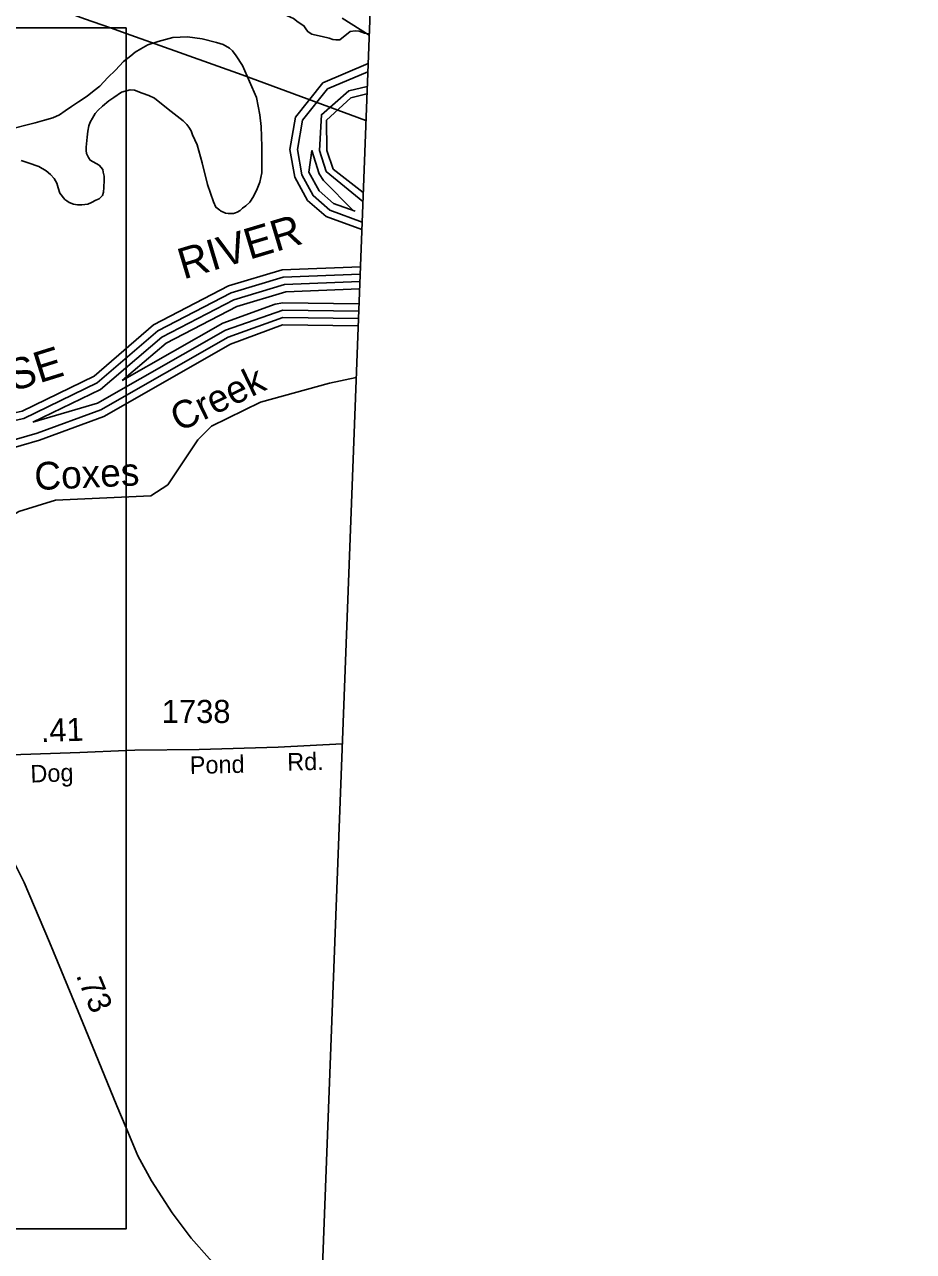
# Model space of a CAD drawing. Extents: x 2206922 to 2357709, y 510027 to 673830.
# Drawn here: x 2347243 to 2352056, y 535608 to 542251 of the extents above; entities that cross this region are included whole.
import ezdxf

# ---------------------------------------------------------------- set-up
doc = ezdxf.new("R2010")
doc.units = 0
for name, color, linetype in [('Exist Boundary Political CountyLine', 7, 'Continuous'), ('Exist Hydrographic Buffer Line', 7, 'Continuous'), ('Exist Hydrographic Creek Single Shore', 7, 'Continuous'), ('Exist Hydrographic Creek Single Shore Label', 7, 'Continuous'), ('Exist Hydrographic Misc Water Feature', 7, 'Continuous'), ('Exist Hydrographic River Shore', 7, 'Continuous'), ('Exist Hydrographic River Shore Label', 7, 'Continuous'), ('Exist Road Primary NC Attributed', 7, 'Continuous'), ('Exist Road Primary NC Service Mileage Hundredths English Label', 7, 'Continuous'), ('Exist Road Secondary Mileage Hundredths English Label', 7, 'Continuous'), ('Exist Road Secondary Type 51 Attributed', 7, 'Continuous'), ('Exist Road Secondary Type 51 Label', 7, 'Continuous'), ('Exist Road Secondary Type 51 Number Label', 7, 'Continuous'), ('Exist Utilities Electrical Transmission Line', 7, 'Continuous'), ('Map Preparation Inset Cut Line', 7, 'Continuous')]:
    doc.layers.add(name, color=color, linetype=linetype)

msp = doc.modelspace()

# ---------------------------------------------------------------- linework, layer by layer
at = {"layer": 'Exist Boundary Political CountyLine'}
msp.add_lwpolyline([(2352055.7, 585131.1), (2350627.1, 582133.9), (2348329.9, 521702.6)], dxfattribs=at)
at = {"layer": 'Exist Hydrographic Buffer Line'}
for points in [[(2349070.3, 541181.2), (2348895.6, 541246.6), (2348805.8, 541324.7), (2348744.3, 541438), (2348719.9, 541574.5), (2348747.6, 541732.6), (2348883.1, 541903.1), (2349101.3, 541995.5)], [(2349098.2, 541915.1), (2348999.4, 541892.4), (2348850.1, 541762.9), (2348839, 541568.9), (2348875.1, 541456.2), (2349074.5, 541292.4)], [(2349032.1, 541240.2), (2348916.3, 541281.7), (2348837.6, 541350.2), (2348782.6, 541451.4), (2348799, 541568.3), (2348837.4, 541443.3), (2348861.6, 541407.6), (2349022.1, 541243.8)], [(2346788.3, 540020.9), (2347238.6, 540118.3), (2347636.6, 540311), (2347963.6, 540592.4), (2348361, 540798.5), (2348643.8, 540883.2), (2349059.6, 540899.9)], [(2347287.4, 540098.5), (2347654, 540275), (2347986.4, 540559.1), (2348376.4, 540761.2), (2348650.4, 540843.4), (2349058.1, 540859.8)], [(2347770.9, 540323.4), (2348008.8, 540525.8), (2348391.4, 540723.9), (2348657.1, 540803.6), (2349056.6, 540819.7)], [(2349053.5, 540739.4), (2348641.3, 540744.4), (2348599.1, 540737.2), (2348316.9, 540633.8), (2347770.9, 540323.4)], [(2349052, 540699.7), (2348640.9, 540704.4), (2348330.7, 540596.2), (2347638, 540201.9), (2347287.4, 540098.5)], [(2349050.5, 540660), (2348640.5, 540664.4), (2348344.4, 540558.7)], [(2348344.4, 540558.7), (2347655, 540165.6), (2347310.6, 540038.4), (2346918.3, 539925.4), (2346462, 539897.4), (2345988.4, 539997.1), (2345590, 540198.4), (2345409.1, 540256.1), (2344967, 540302.7), (2343412.7, 540217.4), (2342470.3, 540107.1), (2341432.7, 539878.5)]]:
    msp.add_lwpolyline(points, dxfattribs=at)
at = {"layer": 'Exist Hydrographic Creek Single Shore'}
msp.add_lwpolyline([(2346448.6, 538412.7), (2346547.1, 538767.8), (2346619.1, 539026.7), (2346692.1, 539183.9), (2346939, 539446.6), (2347212.1, 539615.1), (2347411, 539675.6), (2347927.1, 539699.7), (2348018.2, 539759.2), (2348181.2, 540002), (2348255, 540077.2), (2348520.2, 540206.1), (2348894.2, 540309.7), (2349038.3, 540339.7)], dxfattribs=at)
at = {"layer": 'Exist Hydrographic Misc Water Feature'}
for points in [[(2349109.1, 542200.2), (2349083.6, 542204.7), (2349053.7, 542214.5), (2349033.6, 542216.3), (2349005.5, 542214), (2348950.1, 542169.2), (2348928.4, 542168.8), (2348912.2, 542170.9), (2348892.3, 542176.7), (2348854, 542186.1), (2348812.1, 542195.6), (2348797.8, 542199.4), (2348783.4, 542207.2), (2348775.7, 542213.3), (2348769.5, 542223.1), (2348755.4, 542244.8), (2348723.4, 542264.5), (2348699, 542284), (2348666.4, 542297.9), (2348642.6, 542313.6), (2348654.1, 542353.6)], [(2349108.8, 542193.5), (2348962, 542284.8)], [(2347194.5, 541692.3), (2347250.5, 541707.1), (2347300.1, 541719.5), (2347350.1, 541734.2), (2347396.1, 541746.8), (2347431.5, 541763), (2347463.3, 541783.7), (2347497.2, 541807.8), (2347534.9, 541832.2), (2347582.5, 541862.7), (2347620.2, 541893.6), (2347649.7, 541917.9), (2347693.2, 541964.1), (2347734.8, 542004.4), (2347778.3, 542051), (2347817.6, 542081.6), (2347841.4, 542101.9), (2347873, 542120.3), (2347910.9, 542140.6), (2347966.7, 542159.3), (2348046.3, 542180.2), (2348124.4, 542185.1), (2348204.2, 542174.3), (2348282.3, 542153.2), (2348318.6, 542143.8), (2348352.6, 542124), (2348369.2, 542108.1), (2348389.1, 542082.5), (2348422.3, 542028.8), (2348498, 541856), (2348516.9, 541762.4), (2348523.6, 541698.5), (2348527.3, 541590.5), (2348526.7, 541476.6), (2348526.7, 541448.6), (2348517.5, 541398.5), (2348502.1, 541362.3), (2348482.8, 541319.8), (2348462.9, 541289.9), (2348440.8, 541269.7), (2348423.6, 541257.3), (2348409.6, 541245.2), (2348393.4, 541235.1), (2348385.6, 541231), (2348373.7, 541228.8), (2348345.7, 541228.5), (2348331.5, 541230.3), (2348303.6, 541241.7), (2348299.7, 541245.9), (2348279.2, 541261.6), (2348265.1, 541291.3), (2348233.9, 541384.8), (2348204.2, 541502.4), (2348177.1, 541600.2), (2348152.5, 541653.7), (2348144.1, 541675.7), (2348132.2, 541695.7), (2348122.1, 541709.4), (2348101.6, 541729.1), (2348037.1, 541780.6), (2347956.7, 541843.4), (2347946.4, 541853.4), (2347915.9, 541866.9), (2347880.4, 541880.4), (2347837.9, 541896.1), (2347814, 541897.7), (2347768, 541885.1), (2347726.2, 541856.5), (2347698.7, 541838.3), (2347664.9, 541809.8), (2347641.3, 541787.8), (2347625.5, 541769.4), (2347610.1, 541743.4), (2347597.8, 541723.4), (2347590.2, 541703), (2347584.5, 541673.1), (2347581.2, 541641.1), (2347576.1, 541586.7), (2347576.1, 541568.9), (2347578.1, 541553.2), (2347588.4, 541531.3), (2347598.4, 541517.3), (2347647, 541489.7), (2347667.3, 541466), (2347669.2, 541452.3), (2347673.7, 541430.1), (2347673.7, 541408.2), (2347672.3, 541368.3), (2347670.8, 541344.2), (2347664.9, 541326), (2347646.8, 541308), (2347629, 541299.8), (2347605.2, 541287.5), (2347585.1, 541279.2), (2347553.5, 541275.1)], [(2347553.5, 541275.1), (2347529.5, 541274.6), (2347507.6, 541278.3), (2347483.4, 541288), (2347471.5, 541295.9), (2347460.9, 541303.6), (2347434.6, 541337.5), (2347424.4, 541367.1), (2347418, 541393.1), (2347403.6, 541416.8), (2347383.6, 541438.9), (2347359.6, 541458.3), (2347319.2, 541481.8), (2347263, 541503.2), (2347224.8, 541514.7)]]:
    msp.add_lwpolyline(points, dxfattribs=at)
at = {"layer": 'Exist Hydrographic River Shore'}
for points in [[(2349068.8, 541141.9), (2348875.1, 541211.4), (2348774.2, 541299.3), (2348706.1, 541424.5), (2348679.1, 541574.4), (2348710, 541749.6), (2348858.1, 541936), (2349102.9, 542039.6)], [(2349076.4, 541342.4), (2348913, 541468.9), (2348879.2, 541569.4), (2348877.2, 541733.4), (2349009.2, 541853.5), (2349096.7, 541875.4)], [(2345183.8, 540475.9), (2345469, 540444.1), (2346004, 540268.7), (2346289, 540122.7), (2346507.2, 540072.4), (2346790.1, 540060.8), (2347230.2, 540157.3), (2347619.2, 540346.9), (2347941.1, 540625.8), (2348346.1, 540835.7), (2348637, 540922.9), (2349061.1, 540940)], [(2338557.9, 540277), (2338975, 540215), (2340944.9, 539841.6), (2341437, 539838.4), (2342475, 540067.4), (2343415, 540177.4), (2344963.1, 540262.9), (2345397, 540218), (2345572.1, 540162.7), (2345975, 539959), (2346459, 539857.1), (2346925.1, 539885.8), (2347323.1, 540000.3), (2347672.1, 540129.2), (2348358.2, 540521.1), (2348640.1, 540624.4), (2349049, 540620.3)]]:
    msp.add_lwpolyline(points, dxfattribs=at)
at = {"layer": 'Exist Road Primary NC Attributed'}
msp.add_lwpolyline([(2348841.3, 535157.1), (2348672.3, 535239.3), (2348506.9, 535342.5), (2348351.2, 535469.1), (2348244.1, 535568.4), (2348145.1, 535679.4), (2348041.9, 535817.4), (2347930.7, 535991), (2347856.8, 536125.4), (2347792.3, 536278.2), (2347741.9, 536397.4), (2347625.3, 536683.8), (2347520.2, 536937.9), (2347377.6, 537282.6), (2347240.5, 537605.8), (2347127.4, 537834.1), (2347014.3, 538025.6), (2346895.3, 538162.6), (2346790.1, 538279.7)], dxfattribs=at)
at = {"layer": 'Exist Road Secondary Type 51 Attributed'}
msp.add_lwpolyline([(2346790.1, 538279.7), (2347171, 538297.5), (2347542, 538310.4), (2347792.3, 538320.5), (2347839.6, 538322.4), (2348187.7, 538326.1), (2348615.9, 538337.8), (2348963, 538357.2)], dxfattribs=at)
at = {"layer": 'Exist Utilities Electrical Transmission Line'}
msp.add_line((2347708, 542232.7), (2347792.3, 542202.7), dxfattribs=at)
for points in [[(2345717.2, 542967.1), (2346240.1, 542772.6), (2347567.4, 542282.7), (2347708, 542232.7)], [(2347792.3, 542202.7), (2348420.7, 541979.2), (2349091.2, 541731.5)]]:
    msp.add_lwpolyline(points, dxfattribs=at)
at = {"layer": 'Map Preparation Inset Cut Line'}
for p, q in [((2343935, 542232.7), (2347708, 542232.7)), ((2347792.3, 542202.7), (2347792.3, 538320.5)), ((2347792.3, 538320.5), (2347792.3, 536278.2))]:
    msp.add_line(p, q, dxfattribs=at)
for points in [[(2347708, 542232.7), (2347792.3, 542232.7), (2347792.3, 542202.7)], [(2347792.3, 536278.2), (2347792.3, 535730.4), (2344992.6, 535730.4)]]:
    msp.add_lwpolyline(points, dxfattribs=at)

# ---------------------------------------------------------------- texts
at = {"layer": 'Exist Hydrographic Creek Single Shore Label'}
for s, rotation, p in [('Creek', 25.91452, (2348079.5, 540043.3)), ('Coxes', 2.67841, (2347299, 539730))]:
    msp.add_text(s, height=150, rotation=rotation, dxfattribs=at).set_placement(p)
at = {"layer": 'Exist Hydrographic River Shore Label'}
for s, rotation, p in [('RIVER', 16.6825, (2348103.1, 540870.2)), ('NEUSE', 17.36028, (2346729.7, 540122.8))]:
    msp.add_text(s, height=167.32, rotation=rotation, dxfattribs=at).set_placement(p)
at = {"layer": 'Exist Road Primary NC Service Mileage Hundredths English Label'}
msp.add_text('.73', height=125, rotation=292.46758, dxfattribs=at).set_placement((2347519.4, 537103.3))
at = {"layer": 'Exist Road Secondary Mileage Hundredths English Label'}
msp.add_text('.41', height=125, rotation=1.99173, dxfattribs=at).set_placement((2347332.4, 538365.7))
at = {"layer": 'Exist Road Secondary Type 51 Label'}
for s, rotation, p in [('Pond', 1.23769, (2348138.3, 538193.6)), ('Rd.', 1.30723, (2348665.8, 538211.3)), ('Dog', 1.98101, (2347276.1, 538146.7))]:
    msp.add_text(s, height=95, rotation=rotation, dxfattribs=at).set_placement(p)
at = {"layer": 'Exist Road Secondary Type 51 Number Label'}
msp.add_text('1738', height=125, dxfattribs=at).set_placement((2347985.8, 538469.5))

doc.saveas('drawing.dxf')
